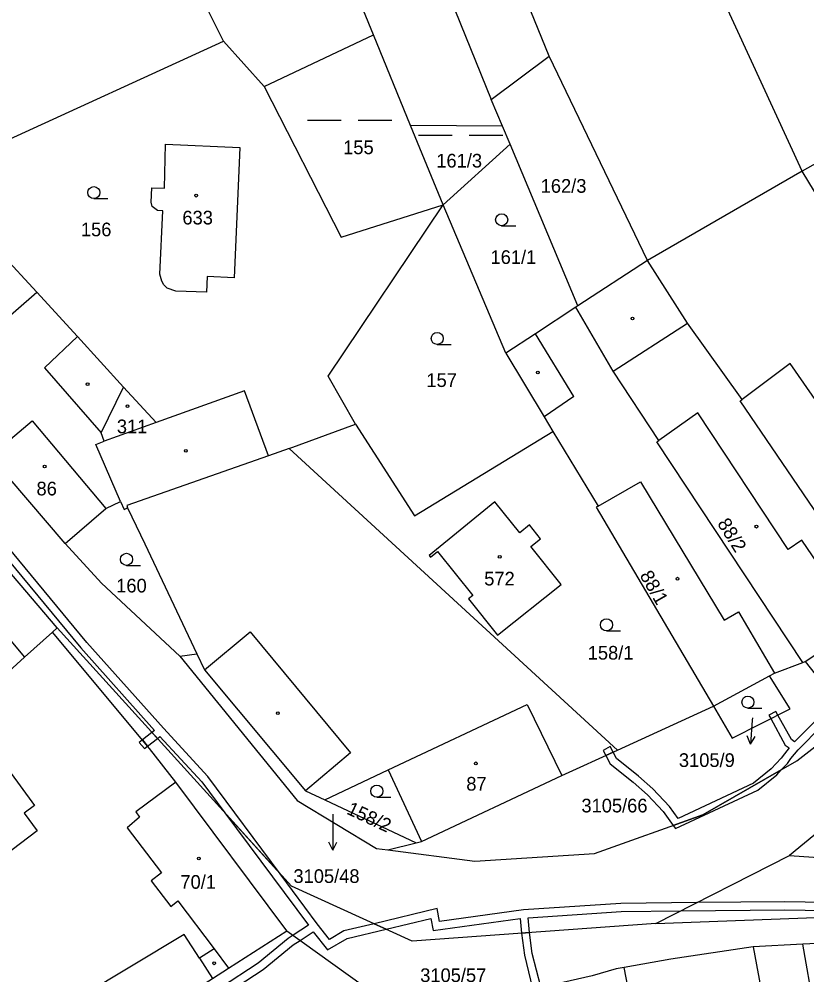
# Model space of a CAD drawing. Extents: x -776734 to -748832, y -1118122 to -976986.
# Drawn here: x -753275.1 to -753177.2, y -1115665 to -1115546.1 of the extents above; entities that cross this region are included whole.
import ezdxf

# ---------------------------------------------------------------- set-up
doc = ezdxf.new("R2010")
doc.units = 0
for name, color, linetype in [('KM_Hranice parcel', 7, 'Continuous'), ('KM_Parcelní čísla', 7, 'Continuous'), ('KM_Pop  PČ popisy', 7, 'Continuous'), ('KM_Vnitřní kresba', 7, 'Continuous'), ('KM_Věcná břemena k části', 7, 'Continuous'), ('KM_Značky budov', 7, 'Continuous'), ('KM_Značky kultur', 7, 'Continuous')]:
    doc.layers.add(name, color=color, linetype=linetype)

msp = doc.modelspace()

# ---------------------------------------------------------------- linework, layer by layer
at = {"layer": 'KM_Hranice parcel'}
for p, q in [((-753234.72, -1115511.09), (-753216.41, -1115556.11)), ((-753177.75, -1115565.03), (-753202.17, -1115512.06)), ((-753282.73, -1115563.93), (-753249.7, -1115548.87)), ((-753249.7, -1115548.87), (-753244.65, -1115554.51)), ((-753244.65, -1115554.51), (-753231.06, -1115548.08)), ((-753226.44, -1115559.33), (-753231.06, -1115548.08)), ((-753216.41, -1115556.11), (-753209.2, -1115550.73)), ((-753197, -1115576.13), (-753209.2, -1115550.73)), ((-753215.02, -1115559.42), (-753216.41, -1115556.11)), ((-753163.74, -1115557.11), (-753177.75, -1115565.03)), ((-753222.38, -1115569.21), (-753226.44, -1115559.33)), ((-753215.02, -1115559.42), (-753226.44, -1115559.33)), ((-753214.08, -1115561.66), (-753215.02, -1115559.42)), ((-753214.08, -1115561.66), (-753222.38, -1115569.21)), ((-753205.64, -1115581.77), (-753214.08, -1115561.66)), ((-753177.75, -1115565.03), (-753197, -1115576.13)), ((-753214.62, -1115587.64), (-753222.38, -1115569.21)), ((-753197, -1115576.13), (-753205.64, -1115581.77)), ((-753205.64, -1115581.77), (-753205.91, -1115581.95)), ((-753258.08, -1115596.29), (-753262.14, -1115591.87)), ((-753258.08, -1115596.29), (-753264.55, -1115598.61)), ((-753241.56, -1115599.5), (-753233.3, -1115596.48)), ((-753200.72, -1115637), (-753241.56, -1115599.5)), ((-753136.11, -1115614.27), (-753179.32, -1115650.12)), ((-753270.99, -1115622.34), (-753270.4, -1115621.81)), ((-753177.39, -1115626), (-753171.29, -1115621.92)), ((-753255.12, -1115625.31), (-753253.04, -1115625.06)), ((-753177.67, -1115626.11), (-753177.39, -1115626)), ((-753188.8, -1115631.54), (-753181.82, -1115627.79)), ((-753200.72, -1115637), (-753188.8, -1115631.54)), ((-753237.13, -1115643.2), (-753225.74, -1115648.54)), ((-753229.28, -1115649.43), (-753225.74, -1115648.54)), ((-753225.74, -1115648.54), (-753225.09, -1115648.37)), ((-753195.95, -1115658.56), (-753179.32, -1115650.12)), ((-753241.82, -1115659.5), (-753227.74, -1115669.55)), ((-753177.69, -1115661.16), (-753183.86, -1115661.48))]:
    msp.add_line(p, q, dxfattribs=at)
for points in [[(-753249.7, -1115548.87), (-753261.94, -1115524.38), (-753265.56, -1115514.39), (-753267.01, -1115503.74)], [(-753231.06, -1115548.08), (-753241.68, -1115522.2), (-753243.16, -1115517.97), (-753243.86, -1115514.53), (-753244.42, -1115511.25)], [(-753209.2, -1115550.73), (-753217.86, -1115529.4), (-753224.81, -1115511.39)], [(-753244.65, -1115554.51), (-753235.08, -1115573.23), (-753222.38, -1115569.21)], [(-753257.12, -1115579.16), (-753257.38, -1115578.71), (-753257.62, -1115577.84), (-753257.25, -1115569.96), (-753257.93, -1115569.93), (-753258.59, -1115569.41), (-753258.69, -1115568.88), (-753258.63, -1115567.09), (-753257.03, -1115567.12), (-753256.92, -1115561.67), (-753247.66, -1115562.1), (-753248.37, -1115578.29), (-753251.73, -1115578.14), (-753251.83, -1115580.08), (-753255.62, -1115579.96), (-753256.73, -1115579.56), (-753257.12, -1115579.16)], [(-753154.26, -1115600.52), (-753166.3, -1115584.48), (-753166.06, -1115584.3), (-753177.75, -1115565.03)], [(-753233.3, -1115596.48), (-753236.71, -1115590.51), (-753222.38, -1115569.21)], [(-753262.14, -1115591.87), (-753267.88, -1115585.6), (-753272.94, -1115580.07), (-753277.35, -1115575.25), (-753283.1, -1115580.34)], [(-753167.75, -1115619.56), (-753185.47, -1115593.58), (-753185.23, -1115593.41), (-753192, -1115583.91), (-753197, -1115576.13)], [(-753205.91, -1115581.95), (-753210.93, -1115585.24), (-753214.62, -1115587.64)], [(-753177.67, -1115626.11), (-753195.83, -1115598.68), (-753195.58, -1115598.52), (-753201.26, -1115589.89), (-753205.91, -1115581.95)], [(-753269.38, -1115611.32), (-753278.71, -1115600.47), (-753282.21, -1115596.4), (-753282.13, -1115596.33), (-753283.67, -1115594.26), (-753285.79, -1115591.29), (-753289.87, -1115586.17)], [(-753214.62, -1115587.64), (-753209.84, -1115595.55), (-753208.74, -1115597.38)], [(-753264.55, -1115598.61), (-753264.92, -1115597.56), (-753262.14, -1115591.87)], [(-753241.56, -1115599.5), (-753244.12, -1115600.41), (-753247.09, -1115592.35), (-753258.08, -1115596.29)], [(-753229.28, -1115649.43), (-753218.46, -1115650.82), (-753203.57, -1115649.85), (-753190.12, -1115645.06), (-753178.4, -1115638.36), (-753146, -1115613.14), (-753122.36, -1115596.14)], [(-753233.3, -1115596.48), (-753225.98, -1115607.89), (-753208.74, -1115597.38)], [(-753208.74, -1115597.38), (-753203.12, -1115606.67), (-753203.39, -1115606.82), (-753188.8, -1115631.54)], [(-753262.5, -1115606.08), (-753265.6, -1115598.99), (-753264.55, -1115598.61)], [(-753270.4, -1115621.81), (-753277.48, -1115613.47), (-753280.65, -1115609.85), (-753284.54, -1115605.39)], [(-753269.38, -1115611.32), (-753264.36, -1115606.96), (-753262.5, -1115606.08)], [(-753262.5, -1115606.08), (-753262.07, -1115607.08), (-753261.66, -1115606.9), (-753259.51, -1115611.36), (-753253.04, -1115625.06)], [(-753211.51, -1115611.7), (-753210.29, -1115610.73), (-753211.65, -1115609.01), (-753212.87, -1115610), (-753215.97, -1115606.16), (-753224.13, -1115612.81), (-753223.97, -1115613.01), (-753223.1, -1115612.3), (-753218.69, -1115617.8), (-753219.23, -1115618.22), (-753215.64, -1115622.7), (-753207.74, -1115616.41), (-753211.51, -1115611.7)], [(-753269.38, -1115611.32), (-753264.86, -1115616.26), (-753255.12, -1115625.31)], [(-753270.99, -1115622.34), (-753274.45, -1115625.46), (-753278.36, -1115628.98), (-753288.39, -1115638.01)], [(-753241.82, -1115659.5), (-753255.62, -1115641.01), (-753258.9, -1115636.83), (-753270.99, -1115622.34)], [(-753195.95, -1115658.56), (-753226.24, -1115660.75), (-753241.26, -1115653.94), (-753270.4, -1115621.81)], [(-753177.39, -1115626), (-753174.74, -1115629.33), (-753168.89, -1115625.79), (-753171.29, -1115621.92)], [(-753255.12, -1115625.31), (-753240.57, -1115643.26), (-753230.7, -1115649.25), (-753229.28, -1115649.43)], [(-753253.04, -1115625.06), (-753252.08, -1115627.01), (-753239.5, -1115642.09), (-753237.13, -1115643.2)], [(-753181.82, -1115627.79), (-753181.19, -1115627.45), (-753177.67, -1115626.11)], [(-753188.8, -1115631.54), (-753186.44, -1115635.52), (-753179.25, -1115631.87), (-753181.82, -1115627.79)], [(-753225.09, -1115648.37), (-753207.63, -1115640.17), (-753200.72, -1115637)], [(-753277.76, -1115640.45), (-753276.46, -1115639.48), (-753273.21, -1115643.89), (-753274.49, -1115644.85)], [(-753237.13, -1115643.2), (-753229.24, -1115639.48), (-753225.09, -1115648.37)], [(-753274.49, -1115644.85), (-753272.86, -1115647.05), (-753281.38, -1115653.49)], [(-753179.32, -1115650.12), (-753155.44, -1115651.77), (-753135.02, -1115658.59), (-753119.51, -1115664.13), (-753111.17, -1115663.8)], [(-753195.95, -1115658.56), (-753170.6, -1115657.6), (-753158.05, -1115658.17), (-753146.25, -1115660.37), (-753124.98, -1115669.67)], [(-753269.63, -1115676.89), (-753268.09, -1115676.28), (-753251.08, -1115665.42), (-753249.07, -1115664.14), (-753241.82, -1115659.5)], [(-753183.86, -1115661.48), (-753194.07, -1115663.02), (-753199.9, -1115664.05), (-753200.87, -1115664.22), (-753203.86, -1115665.09), (-753208.41, -1115666.11)], [(-753183.86, -1115661.48), (-753182.68, -1115667.73), (-753182.62, -1115669.25), (-753179.68, -1115689.67), (-753177.21, -1115705.79), (-753177.75, -1115705.89)], [(-753164.8, -1115660.63), (-753164.96, -1115669.23), (-753176.29, -1115668.95), (-753177.69, -1115661.16)], [(-753164.8, -1115660.63), (-753170.83, -1115660.82), (-753177.69, -1115661.16)]]:
    msp.add_lwpolyline(points, dxfattribs=at)
at = {"layer": 'KM_Pop  PČ popisy'}
for p, q in [((-753183.97, -1115633.27), (-753184.179, -1115636.264)), ((-753183.95, -1115632.99), (-753183.97, -1115633.27)), ((-753184.179, -1115636.264), (-753184.609, -1115635.23)), ((-753184.179, -1115636.264), (-753183.61, -1115635.3)), ((-753236.1, -1115644.97), (-753236.11, -1115646.44)), ((-753236.11, -1115646.44), (-753236.11, -1115649.441)), ((-753236.11, -1115649.441), (-753236.611, -1115648.44)), ((-753236.11, -1115649.441), (-753235.609, -1115648.44))]:
    msp.add_line(p, q, dxfattribs=at)
at = {"layer": 'KM_Vnitřní kresba'}
for p, q in [((-753285.79, -1115591.29), (-753272.94, -1115580.07)), ((-753201.26, -1115589.89), (-753192, -1115583.91)), ((-753267.88, -1115585.6), (-753271.96, -1115589.48)), ((-753206.14, -1115593.04), (-753210.93, -1115585.24)), ((-753179.24, -1115588.92), (-753185.23, -1115593.41)), ((-753168.45, -1115604.56), (-753179.24, -1115588.92)), ((-753271.96, -1115589.48), (-753264.92, -1115597.56)), ((-753206.14, -1115593.04), (-753209.84, -1115595.55)), ((-753190.75, -1115595.07), (-753195.58, -1115598.52)), ((-753179.49, -1115612.05), (-753190.75, -1115595.07)), ((-753278.71, -1115600.47), (-753273.52, -1115596.07)), ((-753273.52, -1115596.07), (-753264.36, -1115606.96)), ((-753244.12, -1115600.41), (-753261.73, -1115606.61)), ((-753203.12, -1115606.67), (-753197.85, -1115603.67)), ((-753197.85, -1115603.67), (-753187.44, -1115620.85)), ((-753261.73, -1115606.61), (-753261.66, -1115606.9)), ((-753177.81, -1115610.91), (-753179.49, -1115612.05)), ((-753170.63, -1115621.48), (-753177.81, -1115610.91)), ((-753281.7, -1115616.86), (-753274.45, -1115625.46)), ((-753187.44, -1115620.85), (-753185.66, -1115619.82)), ((-753185.66, -1115619.82), (-753181.19, -1115627.45)), ((-753252.08, -1115627.01), (-753246.41, -1115622.29)), ((-753246.41, -1115622.29), (-753233.9, -1115637.37)), ((-753229.24, -1115639.48), (-753211.94, -1115631.32)), ((-753211.94, -1115631.32), (-753207.63, -1115640.17)), ((-753233.9, -1115637.37), (-753239.5, -1115642.09)), ((-753255.62, -1115641.01), (-753260.63, -1115644.69)), ((-753260.63, -1115644.69), (-753260.16, -1115645.33)), ((-753260.16, -1115645.33), (-753261.7, -1115646.68)), ((-753261.7, -1115646.68), (-753257.42, -1115652.26)), ((-753257.42, -1115652.26), (-753258.7, -1115653.25)), ((-753258.7, -1115653.25), (-753256.25, -1115656.44)), ((-753256.25, -1115656.44), (-753255.37, -1115655.76)), ((-753255.37, -1115655.76), (-753250.87, -1115661.74)), ((-753254.58, -1115659.93), (-753271.02, -1115669.77)), ((-753252.69, -1115662.89), (-753254.58, -1115659.93)), ((-753250.87, -1115661.74), (-753252.69, -1115662.89)), ((-753250.87, -1115661.74), (-753249.07, -1115664.14)), ((-753252.69, -1115662.89), (-753251.08, -1115665.42)), ((-753198.65, -1115670.44), (-753199.9, -1115664.05))]:
    msp.add_line(p, q, dxfattribs=at)
at = {"layer": 'KM_Věcná břemena k části'}
for points in [[(-753291.06, -1115595.79), (-753267.45, -1115624.29), (-753258.29, -1115634.56), (-753258.61, -1115634.81), (-753257.93, -1115635.56), (-753257.61, -1115635.31), (-753252.41, -1115640.95), (-753249.53, -1115644.82), (-753242.65, -1115652.41), (-753251.64, -1115640.31), (-753257.18, -1115634.3), (-753266.69, -1115623.63), (-753290.34, -1115595.08)], [(-753176.14, -1115633.43), (-753178.69, -1115635.99), (-753179.1, -1115635.7), (-753180.78, -1115632.65), (-753181.02, -1115632.21), (-753181.91, -1115632.66), (-753181.67, -1115633.1), (-753179.86, -1115636.38), (-753179.37, -1115636.74), (-753179.97, -1115637.46), (-753180.37, -1115638.03), (-753181.6, -1115639.34), (-753183.81, -1115641.14), (-753193.19, -1115645.51), (-753194.26, -1115644.03), (-753196.32, -1115641.84), (-753198.11, -1115640.24), (-753200.85, -1115638.06), (-753201.27, -1115637.25), (-753202.18, -1115637.67), (-753201.63, -1115638.72), (-753198.77, -1115640.99), (-753197, -1115642.56), (-753195.04, -1115644.66), (-753193.8, -1115646.37), (-753190.12, -1115645.06), (-753180.36, -1115639.48), (-753179.59, -1115638.66), (-753179.17, -1115638.06), (-753178.27, -1115636.99), (-753175.3, -1115634)], [(-753258.92, -1115673.52), (-753244.78, -1115664.3), (-753241.06, -1115661.24), (-753240.19, -1115660.67), (-753238.55, -1115659.59), (-753236.76, -1115661.84), (-753234.35, -1115660.43), (-753229.5, -1115659.27), (-753230.99, -1115658.6), (-753234.73, -1115659.49), (-753236.52, -1115660.54), (-753238.05, -1115658.6), (-753242.65, -1115652.41), (-753249.53, -1115644.82), (-753239.16, -1115658.79), (-753241.06, -1115660.04), (-753241.65, -1115660.43), (-753245.38, -1115663.5), (-753259.47, -1115672.69)], [(-753167.23, -1115656.07), (-753179.91, -1115655.86), (-753190.85, -1115655.97), (-753200.29, -1115656.07), (-753212.39, -1115656.88), (-753222.84, -1115658.34), (-753223.16, -1115656.72), (-753230.99, -1115658.6), (-753229.5, -1115659.27), (-753223.94, -1115657.94), (-753223.64, -1115659.46), (-753212.81, -1115657.95), (-753212.67, -1115659.77), (-753211.66, -1115659.7), (-753211.81, -1115657.85), (-753200.25, -1115657.07), (-753192.86, -1115656.99), (-753179.92, -1115656.86), (-753167.29, -1115657.07)]]:
    msp.add_lwpolyline(points, dxfattribs=at)
for points in [[(-753257.93, -1115635.56), (-753258.61, -1115634.81), (-753259.8, -1115635.75), (-753259.16, -1115636.52)], [(-753259.16, -1115636.52), (-753259.8, -1115635.75), (-753260.19, -1115636.06), (-753259.55, -1115636.83)], [(-753202.18, -1115637.67), (-753201.27, -1115637.25), (-753201.63, -1115636.58), (-753202.51, -1115637.04)], [(-753183.27, -1115642), (-753180.91, -1115640.07), (-753180.36, -1115639.48), (-753190.12, -1115645.06), (-753193.8, -1115646.37), (-753193.51, -1115646.77)], [(-753210.26, -1115666.45), (-753211.31, -1115662.3), (-753211.66, -1115659.7), (-753212.67, -1115659.77), (-753212.29, -1115662.49), (-753211.3, -1115666.64)]]:
    msp.add_lwpolyline(points, close=True, dxfattribs=at)
at = {"layer": 'KM_Značky budov'}
for centre in [(-753253.1068, -1115568.0692), (-753198.8468, -1115583.3392), (-753210.6168, -1115590.0692), (-753266.6068, -1115591.4992), (-753261.6568, -1115594.2492), (-753254.3968, -1115599.7892), (-753271.9468, -1115601.7392), (-753183.4468, -1115609.2192), (-753215.3668, -1115612.9892), (-753193.2468, -1115615.6992), (-753242.9568, -1115632.4192), (-753218.3368, -1115638.6592), (-753252.7768, -1115650.4992), (-753250.8668, -1115663.5192)]:
    msp.add_circle(centre, 0.175, dxfattribs=at)
at = {"layer": 'KM_Značky kultur'}
for p, q in [((-753239.273, -1115558.67), (-753235.073, -1115558.67)), ((-753232.972, -1115558.67), (-753228.772, -1115558.67)), ((-753225.473, -1115560.56), (-753221.273, -1115560.56)), ((-753219.172, -1115560.56), (-753214.972, -1115560.56)), ((-753265.833, -1115568.44), (-753264.083, -1115568.44)), ((-753215.123, -1115571.81), (-753213.373, -1115571.81)), ((-753223.133, -1115586.57), (-753221.383, -1115586.57)), ((-753261.773, -1115614.04), (-753260.023, -1115614.04)), ((-753202.083, -1115622.18), (-753200.333, -1115622.18)), ((-753184.503, -1115631.79), (-753182.753, -1115631.79)), ((-753230.643, -1115642.86), (-753228.893, -1115642.86))]:
    msp.add_line(p, q, dxfattribs=at)
for centre in [(-753265.8329, -1115567.6898), (-753215.1229, -1115571.0598), (-753223.1329, -1115585.8198), (-753261.7729, -1115613.2898), (-753202.0829, -1115621.4298), (-753184.5029, -1115631.0398), (-753230.6429, -1115642.1098)]:
    msp.add_circle(centre, 0.75, dxfattribs=at)

# ---------------------------------------------------------------- texts
at = {"layer": 'KM_Parcelní čísla'}
for s, p in [('155', (-753234.83, -1115562.91)), ('161/3', (-753223.25, -1115564.57)), ('162/3', (-753210.27, -1115567.71)), ('633', (-753254.82, -1115571.65)), ('156', (-753267.44, -1115573.12)), ('161/1', (-753216.51, -1115576.56)), ('157', (-753224.48, -1115591.86)), ('311', (-753262.97, -1115597.61)), ('86', (-753272.96, -1115605.34)), ('572', (-753217.29, -1115616.54)), ('160', (-753263.05, -1115617.41)), ('158/1', (-753204.42, -1115625.76)), ('3105/9', (-753193.085, -1115639.108)), ('87', (-753219.52, -1115642.05)), ('3105/66', (-753205.206, -1115644.76)), ('3105/48', (-753241.013, -1115653.528)), ('70/1', (-753255.07, -1115654.25)), ('3105/57', (-753225.25, -1115665.85))]:
    msp.add_text(s, height=1.7, dxfattribs=at).set_placement(p)
for s, rotation, p in [('88/2', 302, (-753188.37, -1115608.83)), ('88/1', 300, (-753198.006, -1115615.285)), ('158/2', 335, (-753234.519, -1115644.89))]:
    msp.add_text(s, height=1.7, rotation=rotation, dxfattribs=at).set_placement(p)

doc.saveas('drawing.dxf')
